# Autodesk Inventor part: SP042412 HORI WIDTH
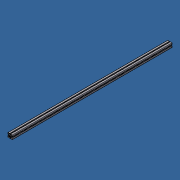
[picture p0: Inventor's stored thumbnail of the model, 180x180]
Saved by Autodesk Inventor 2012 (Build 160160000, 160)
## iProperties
Created: 2013-04
Part Number: SP042412 HORI WIDTH
Material: Aluminum-6061
Description: PROFILE 45X45 UL
Document SubType Name: Modeling
Designer: Admin
Stock Number: 20.1063 PROFILE 45X45 UL
Density: 2.71 g/cm^3
FINISH: CLEAR ANODIZED
Author: Admin
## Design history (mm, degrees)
sketch "Sketch1"
  geometry: L1 (-4.1, -22.5)-(-4.1, -18) reference; L2 (-4.6, -18)-(-6.8, -18) reference; L3 (-6.8, -18)-(-6.8, -9.5) reference; L4 (-6.8, -9.5)-(-4.5, -7.2) reference; L5 (-4.5, -7.2)-(4.5, -7.2) reference; L6 (4.5, -7.2)-(6.8, -9.5) reference; L7 (6.8, -9.5)-(6.8, -18) reference; L8 (4.1, -18)-(4.1, -22.5) reference; L9 (22.5, -22.5)-(4.4, -22.5) reference; L10 (22.5, -4.4)-(22.5, -22.5) reference; L11 (22.5, -4.1)-(18, -4.1) reference; L12 (18, -4.6)-(18, -6.8) reference; L13 (18, -6.8)-(9.5, -6.8) reference; L14 (9.5, -6.8)-(7.2, -4.5) reference; L15 (7.2, -4.5)-(7.2, 4.5) reference; L16 (7.2, 4.5)-(9.5, 6.8) reference; L17 (9.5, 6.8)-(18, 6.8) reference; L18 (18, 4.1)-(22.5, 4.1) reference; L19 (4.4, 22.5)-(22.5, 22.5) reference; L20 (4.1, 22.5)-(4.1, 18) reference; L21 (4.6, 18)-(6.8, 18) reference; L22 (6.8, 18)-(6.8, 9.5) reference; L23 (6.8, 9.5)-(4.5, 7.2) reference; L24 (4.5, 7.2)-(-4.5, 7.2) reference; L25 (-4.5, 7.2)-(-6.8, 9.5) reference; L26 (-6.8, 9.5)-(-6.8, 18) reference; L27 (-4.1, 18)-(-4.1, 22.5) reference; L28 (-22.5, 4.1)-(-18, 4.1) reference; L29 (-18, 4.6)-(-18, 6.8) reference; L30 (-18, 6.8)-(-9.5, 6.8) reference; L31 (-9.5, 6.8)-(-7.2, 4.5) reference; L32 (-7.2, 4.5)-(-7.2, -4.5) reference; L33 (-7.2, -4.5)-(-9.5, -6.8) reference; L34 (-9.5, -6.8)-(-18, -6.8) reference; L35 (-18, -4.1)-(-22.5, -4.1) reference; L36 (-22.5, -22.5)-(-22.5, -4.4) reference; L37 (-21.1, -6.5)-(-19.4, -6.5) reference; L38 (-19.4, -6.5)-(-19.4, -8.2) reference; L39 (-8.2, -19.4)-(-6.5, -19.4) reference; L40 (-6.5, -19.4)-(-6.5, -21.1) reference; L41 (6.5, -21.1)-(6.5, -19.4) reference; L42 (6.5, -19.4)-(8.2, -19.4) reference; L43 (19.4, -8.2)-(19.4, -6.5) reference; L44 (19.4, -6.5)-(21.1, -6.5) reference; L45 (21.1, 6.5)-(19.4, 6.5) reference; L46 (19.4, 6.5)-(19.4, 8.2) reference; L47 (8.2, 19.4)-(6.5, 19.4) reference; L48 (6.5, 19.4)-(6.5, 21.1) reference; L49 (-6.5, 21.1)-(-6.5, 19.4) reference; L50 (-6.5, 19.4)-(-8.2, 19.4) reference; L51 (-19.4, 8.2)-(-19.4, 6.5) reference; L52 (-19.4, 6.5)-(-21.1, 6.5) reference; L53 (-3.537, -5.8)-(-1.188, -3.451) reference; L54 (-3.451, -1.188)-(-5.8, -3.537) reference; L55 (-5.8, -3.537)-(-5.8, 3.537) reference; L56 (-5.8, 3.537)-(-3.451, 1.188) reference; L57 (-1.188, 3.451)-(-3.537, 5.8) reference; L58 (-3.537, 5.8)-(3.537, 5.8) reference; L59 (3.537, 5.8)-(1.188, 3.451) reference; L60 (3.451, 1.188)-(5.8, 3.537) reference; L61 (5.8, 3.537)-(5.8, -3.537) reference; L62 (5.8, -3.537)-(3.451, -1.188) reference; L63 (1.188, -3.451)-(3.537, -5.8) reference; L64 (3.537, -5.8)-(-3.537, -5.8) reference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; A1 r 3.65 centre (0, 0) between (3.287, 1.588) and (1.588, 3.287) reference; A2 r 3.65 centre (0, 0) between (1.588, 3.287) and (1.188, 3.451) reference; A3 r 3.65 centre (0, 0) between (-1.188, 3.451) and (-3.451, 1.188) reference; A4 r 3.65 centre (0, 0) between (-3.451, -1.188) and (-3.287, -1.588) reference; A5 r 3.65 centre (0, 0) between (-3.287, -1.588) and (-1.188, -3.451) reference; A6 r 3.65 centre (0, 0) between (1.188, -3.451) and (1.588, -3.287) reference; A7 r 3.65 centre (0, 0) between (1.588, -3.287) and (3.451, -1.188) reference; A8 r 3.65 centre (0, 0) between (3.451, 1.188) and (3.287, 1.588) reference
  constraints: 192 end point, 32 horizontal, 30 vertical, 16 point on circle, 8 centre point, 8 parallel, 5 perpendicular, 134 other
extrude "Extrusion1" new body sketch "Sketch1" stored distance "d0" = 1688 (computed from Width, TOP_OVERHANG); taper "d1" = 0 deg
body "Solid1"
other parameters: "TABLE_TOP_THICKNESS" = 12.7 [user parameter], "DEPTH" = 914.4 [user parameter], "LOWER_INSET" = 203.2 [user parameter], "Width" = 1828.8 [user parameter; used in 1 equation term], "Height" = 1066.8 [user parameter], "LEVELER_HEIGHT" = 115.824 [user parameter], "TOP_OVERHANG" = 25.4 [user parameter; used in 1 equation term]
